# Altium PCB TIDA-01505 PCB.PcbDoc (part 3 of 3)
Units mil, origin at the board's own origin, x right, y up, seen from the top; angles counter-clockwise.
Board outline 7874.02 x 6929.13 mil, 2 copper layers (Top Layer, Bottom Layer), stack 62 mil thick; 307 components, 129 nets, 623 pads, 701 vias.
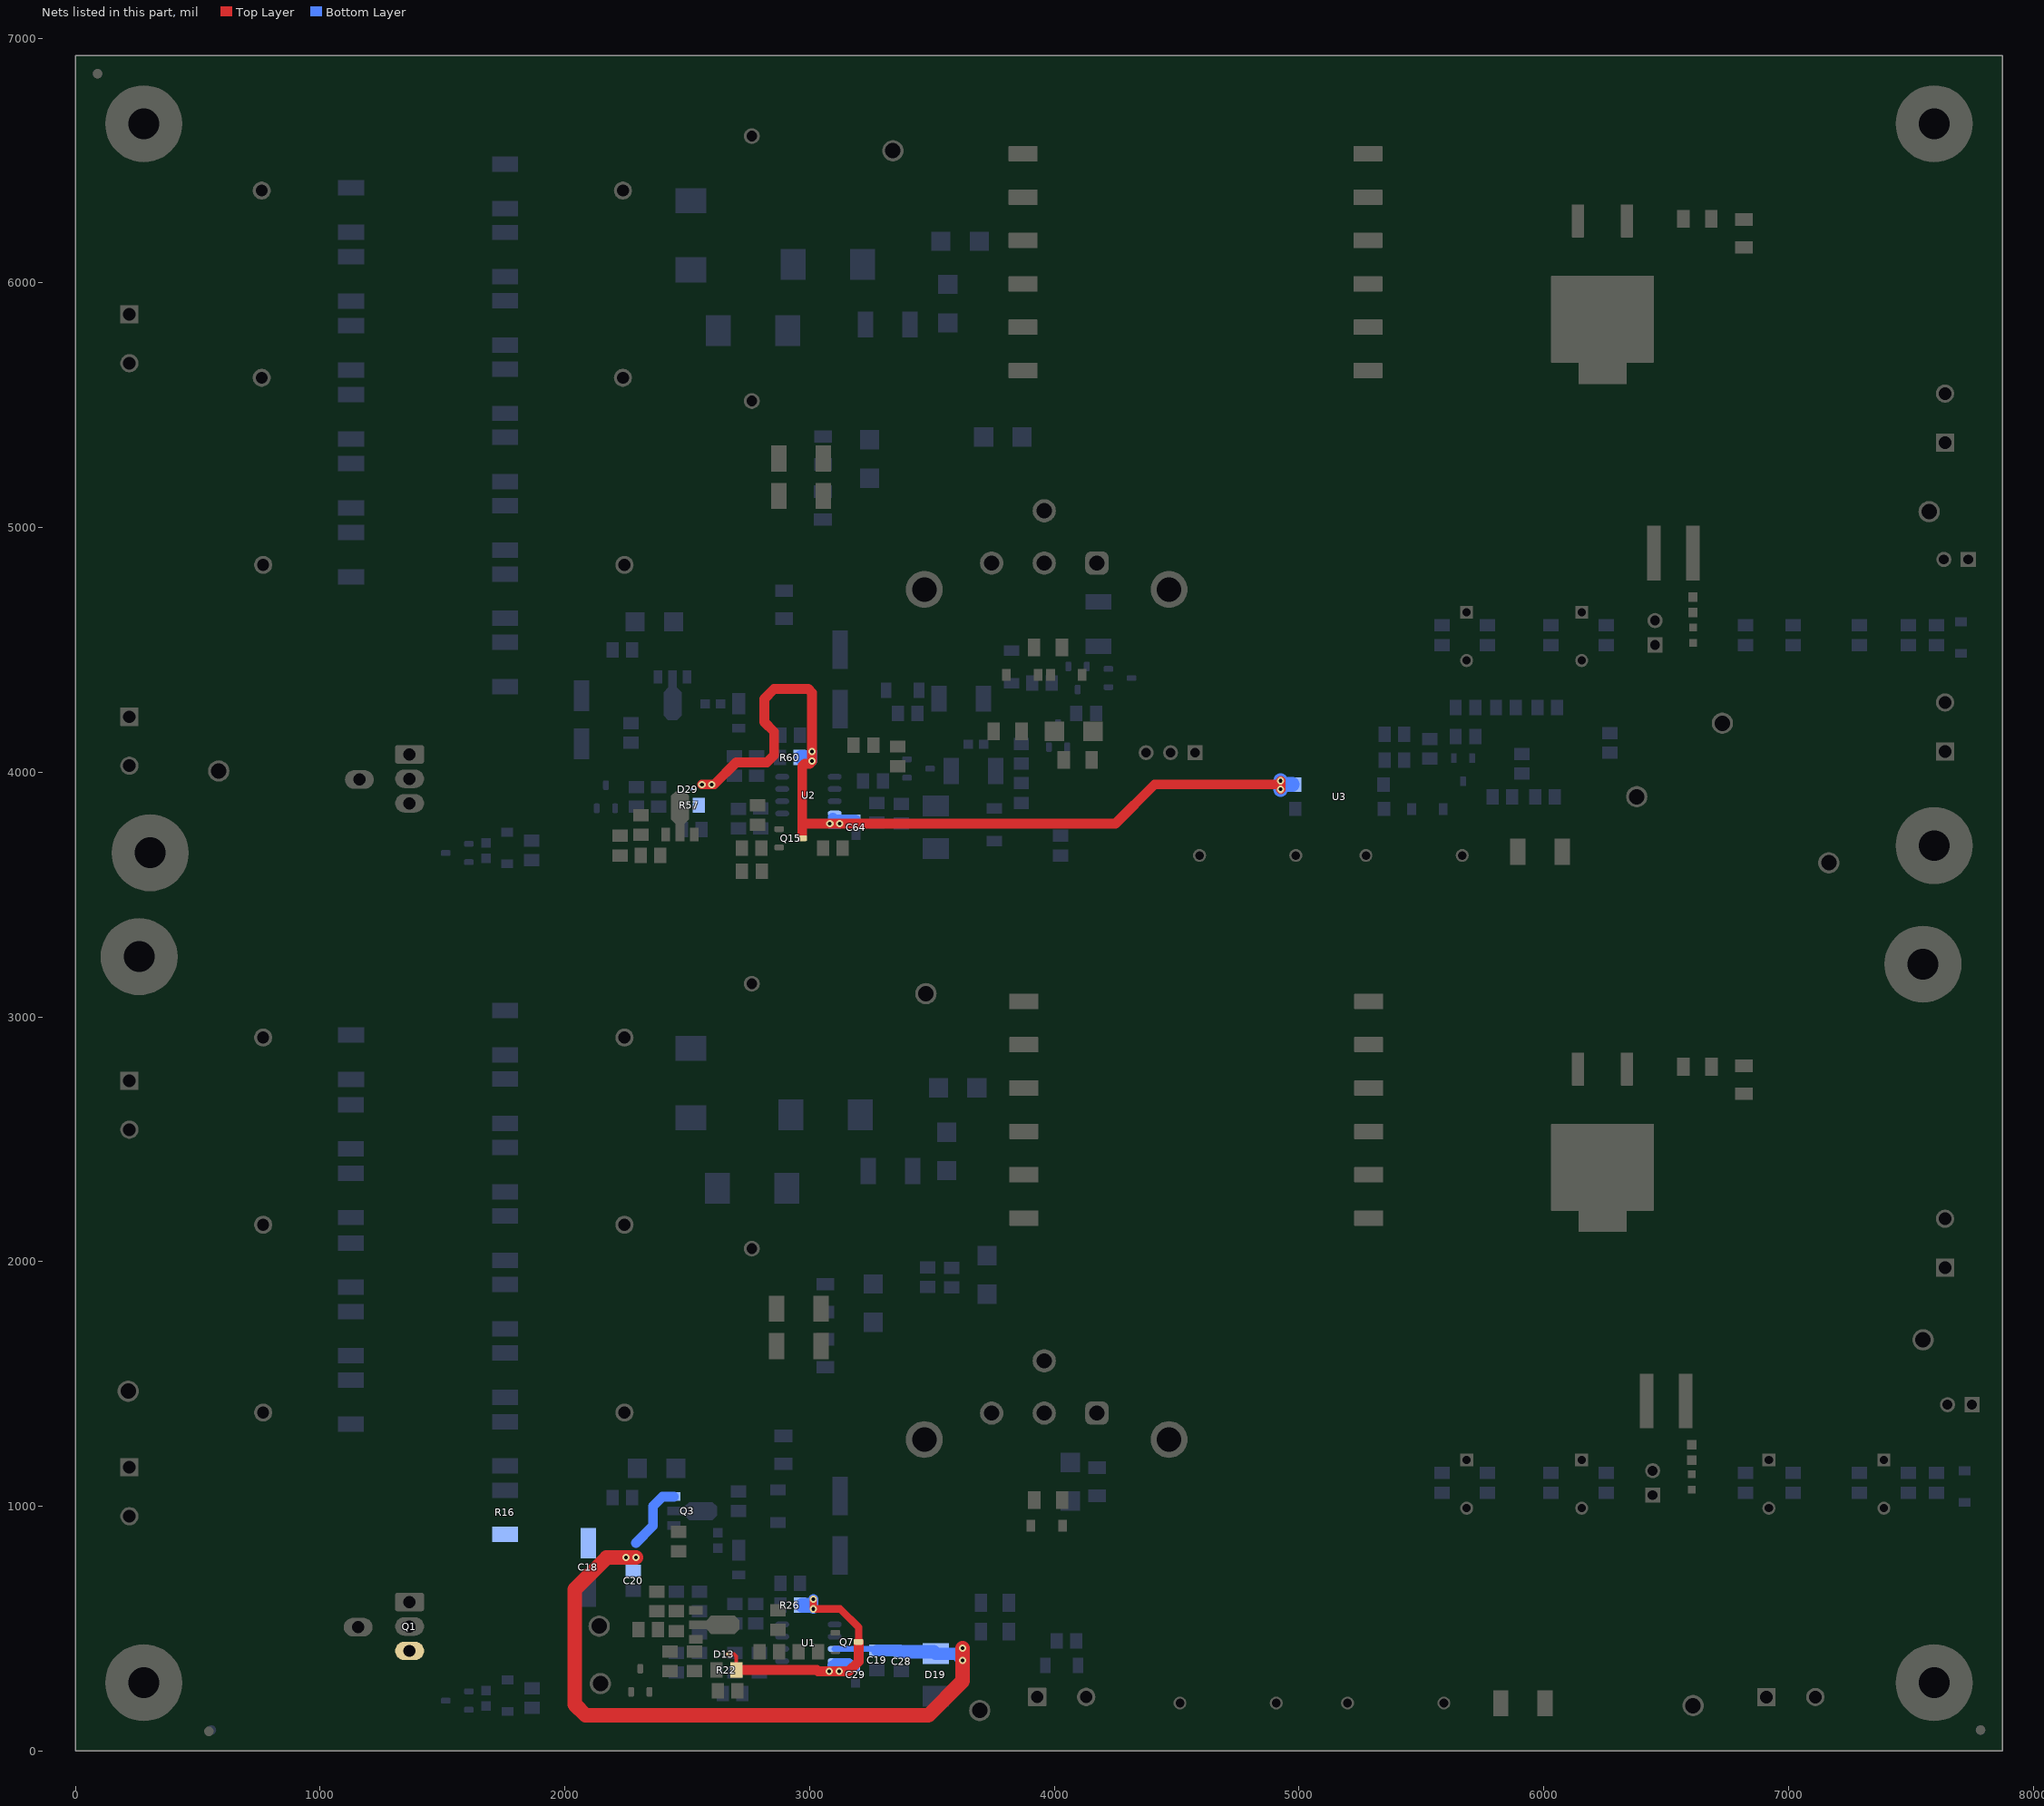
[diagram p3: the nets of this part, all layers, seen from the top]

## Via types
v1: diameter 30, hole 15, Top Layer to Bottom Layer, 666 vias
v2: diameter 20, hole 10, Top Layer to Bottom Layer, 35 vias

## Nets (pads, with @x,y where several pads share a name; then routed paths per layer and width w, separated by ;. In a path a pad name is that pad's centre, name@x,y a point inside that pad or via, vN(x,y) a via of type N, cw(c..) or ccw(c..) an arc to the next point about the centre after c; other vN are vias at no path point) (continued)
VDD_PSR: C18.1 C19.1 C20.1 C28.1 D19.1 Q1.3 Q3.3 R16.1 U1.7 | length 3442.9
  Top Layer w60: v1(2290,790) v1(2250,790) 2170,790 2040,660 2040,190 2085,145 3485,145 3625,285 v1(3625,370) v1(3625,420)
  Bottom Layer w25: U1.7@3102.28,416.65 3268.78,416.65 C19.1@3275,410.43
  Bottom Layer w40: 2290,850 2360,920 2360,1000 2399.06,1039.06 Q3.3@2445.2,1039.06
  Bottom Layer w50: C19.1@3275,410.43 3370,410.43 C28.1@3375,405.43 ; D19.1@3507.01,405.43 D19.1@3515,397.44 3597.56,397.44 v1(3625,370) v1(3625,420)
  Bottom Layer w55: C28.1@3375,405.43 D19.1@3507.01,405.43
VREF: C64.1 D29.1 Q15.3 R57.1 R60.2 U2.8 U3.4 | length 3813.1
  Top Layer w40: v1(2560,3950) v1(2600,3950) 2610,3950 2700,4040 2825,4040 2855,4070 2855,4165 2815,4205 2815,4300 2855,4340 2995,4340 3010,4325 v1(3010,4085) v1(3010,4045) 3000,4035 2980,4035 2970,4025 2970,3790 ; 2970,3745 2970,3790 ; v1(4925,3930) 4925,3950 ; v1(4925,3965) 4925,3950 ; 2970,3790 2970.04,3789.96 v1(3082.56,3789.96) v1(3122.56,3789.96) 4249.96,3789.96 4410,3950 4925,3950
  Bottom Layer w40: 2995,4060 v1(3010,4045) v1(3010,4085) ; v1(3082.56,3789.96) v1(3122.56,3789.96) 3139.06,3806.46 ; 3095,3815 3103.54,3806.46 3139.06,3806.46 ; C64.1@3187.56,3806.46 3139.06,3806.46
  Bottom Layer w60: R60.2@2965,4060 2995,4060 ; v1(4925,3930) v1@4925,3935 ; v1(4925,3965) v1@4925,3935 ; U3.4@4972.55,3950 4940,3950 v1@4925,3935
VREF_PSR: C29.1 D13.1 Q7.3 R22.1 R26.2 U1.8 | length 1353.7
  Top Layer w15: D13.1@2666.54,395.43 2690.12,395.43 2700,385.56 R22.1@2700,330.43
  Top Layer w30: v1(3015,620) v1(3015,580) 3125,580 3199.8,505.2 Q7.3@3199.8,445.39
  Top Layer w40: R22.1@2700,330.43 3029.18,330.43 3034.61,325 v1(3080,325) v1(3120,325) 3160,325 3200,365 3200,445.2 Q7.3@3199.8,445.39
  Bottom Layer w25: U1.8@3102.28,366.65 3162.83,366.65 C29.1@3187.56,341.93
  Bottom Layer w40: 3000,595 v1(3015,580) v1(3015,620) ; v1(3080,325) v1(3120,325) 3136.5,341.5 ; 3092.44,350.04 3100.98,341.5 3136.5,341.5 ; C29.1@3185,341.5 3136.5,341.5
  Bottom Layer w60: R26.2@2970,595 3000,595
pads on no net: FID1.1 FID2.1 FID3.1 FID4.1 FID5.1 FID6.1 H1.1 H2.1 H3.1 H4.1 H5.0 H6.0 H7.0 H8.0 H11.1 H12.0 H13.1 H13.2 H14.1 H14.2 H15.1 H16.0 H17.1 H18.1 H19.0 H20.0 Q1.2 Q6.2 Q9.2 Q14.2 T1.2 T1.7 T1.12 T2.2 T2.7 T2.12 TP6.1

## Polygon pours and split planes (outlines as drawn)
+15Vout on Bottom Layer "BOTTOM_LAYER_+15VOUT_P144" (solid, remove dead copper, pour order 144): 7885,5800 7500,5800 7440,5740 7440,5190 7340,5090 6535,5090 6480,5035 6480,4745 6540,4685 6615,4685 6635,4665 6635,4593.78 6653.78,4575 7859.02,4575 7874.02,4590
Iso_GND on Bottom Layer "BOTTOM_LAYER_ISO_GND_P142" (solid, remove dead copper, pour order 142): 7875,4545 7875,3550.98 7874.02,3550 6090,3550 6045,3595 6045,4170 5850,4365 5290,4365 5220,4435 5220,4505 5260,4545
NetC44_1 on Bottom Layer "BOTTOM_LAYER_NETC44_1_P140" (solid, remove dead copper, pour order 140): 5220,4575 6390,4575 6490,4675 6490,5035 6540,5085 7370,5085 7455,5170 7455,5750 7500,5795 7875,5795 7875,6930 5220.87,6930 5220,6929.13
HV_GND on Bottom Layer "BOTTOM_LAYER_HV_GND_P066" (solid, remove dead copper, pour order 66): 2390,4615 3180,4615 3270,4525 4255,4525 4335,4445 4335,4085 4420,4000 4555,4000 4615,3940 4615,3585 4575,3545 1635,3545 1585,3595 1585,3710 1645,3770 1780,3770 1945,3935 1945,4115 2010,4180 2135,4180 2290,4335 2290,4539.33
Gate_FET on Bottom Layer "BOTTOM_LAYER_GATE_FET_P062" (solid, remove dead copper, pour order 62): 4250,4555 4260,4545 4260,4420 4255,4415 4120,4415 4115,4420 4115,4540 4130,4555
-5V on Bottom Layer "BOTTOM_LAYER_-5V_P060" (solid, remove dead copper, pour order 60): 3950,3900 3965,3915 3995,3915 3995,3855 3972.4,3832.4 3717.6,3832.4 3717.6,3840 3715,3842.6 3715,3880 3735,3900 3755,3900
VREF on Bottom Layer "BOTTOM_LAYER_VREF_P058" (solid, remove dead copper, pour order 58): 2525,3830 2571.56,3830 2581.56,3840 2581.56,3901.56 2595,3915 2620,3915 2625,3920 2625,3955 2610,3970 2525,3970 2510,3955 2510,3908.5 2525,3893.5
NetC61_2 on Bottom Layer "BOTTOM_LAYER_NETC61_2_P056" (solid, remove dead copper, pour order 56): 2205,3885 2195,3875 2195,3835 2200,3830 2485,3830 2495,3840 2495,3930.83 2485.83,3940 2465,3940 2460,3935 2460,3895 2450,3885
NetC42_1 on Bottom Layer "BOTTOM_LAYER_NETC42_1_P052" (solid, remove dead copper, pour order 52): 3295,4655 2605,4655 2565,4615 2565,4410 2550,4395 2550,4345 2795,4345 2875,4425 3375,4425 3415,4385 3415,4210 3425,4200 3465,4200 3485,4220 3485,4465
VDD on Bottom Layer "BOTTOM_LAYER_VDD_P046" (solid, pour order 46): 1330,3910 1315,3895 1315,3850 1330,3835 1665,3835 1750,3920 1750,4185 1815,4250 2200,4250 2242.56,4207.44 2242.56,4182.44 2250,4175 2310,4175 2315,4180 2315,4315 2250,4380 2165,4380 1702.01,4380 1665,4342.99 1665,3970 1605,3910
NetR50_1 on Bottom Layer "BOTTOM_LAYER_NETR50_1_P040" (solid, pour order 40): 1699.29,4660 1812.99,4660 1830,4642.99 1830,4517.99 1812.01,4500 1692.99,4500 1680,4512.99 1680,4643.13
NetQ9_2 on Bottom Layer "BOTTOM_LAYER_NETQ9_2_P038" (solid, pour order 38): 1636.3,4940.51 1807.99,4940.51 1827.99,4920.51 1827.99,4795 1812.99,4780 1630,4780 1615,4795 1615,4921.88
NetR45_1 on Bottom Layer "BOTTOM_LAYER_NETR45_1_P036" (solid, pour order 36): 1700.21,5221.3 1810,5221.3 1830,5201.3 1830,5078.7 1807.09,5055.79 1698.9,5055.79 1680,5074.69 1680,5203.62
NetR43_1 on Bottom Layer "BOTTOM_LAYER_NETR43_1_P034" (solid, pour order 34): 1700.21,5500.51 1810,5500.51 1830,5480.51 1830,5357.91 1802.09,5330 1703.9,5330 1680,5353.9 1680,5482.83
NetR42_1 on Bottom Layer "BOTTOM_LAYER_NETR42_1_P032" (solid, pour order 32): 1700.21,5780.51 1810,5780.51 1830,5760.51 1830,5637.91 1802.09,5610 1703.9,5610 1680,5633.9 1680,5762.83
NetR40_1 on Bottom Layer "BOTTOM_LAYER_NETR40_1_P030" (solid, pour order 30): 1700.21,6060.51 1810,6060.51 1830,6040.51 1830,5917.91 1802.09,5890 1703.9,5890 1680,5913.9 1680,6042.83
NetR38_1 on Bottom Layer "BOTTOM_LAYER_NETR38_1_P020" (solid, pour order 20): 1700.21,6340.51 1810,6340.51 1830,6320.51 1830,6197.91 1802.09,6170 1703.9,6170 1680,6193.9 1680,6322.83
NetC41_2 on Bottom Layer "BOTTOM_LAYER_NETC41_2_P018" (solid, pour order 18): 716.11,5665 840,5665 875,5630 875,5470 925,5420 930,5420 962.92,5387.08 1065.31,5387.08 1073.23,5395 1181.18,5395 1200,5376.18 1200,5245 1185,5230 1066.26,5230 1061.26,5235 965,5235 875,5145 875,4850 820,4795 715,4795 675,4835 675,5628
NetQ9_1 on Bottom Layer "BOTTOM_LAYER_NETQ9_1_P016" (solid, pour order 16): 1192.48,4835 1215,4812.48 1215,4505 1425,4295 1425,4045 1415,4035 1316.11,4035 1306.11,4045 1306.11,4113.89 1305,4115 1305,4175 1045,4435 1045,4485 1045,4810 1070,4835
NetR48_1 on Bottom Layer "BOTTOM_LAYER_NETR48_1_P014" (solid, pour order 14): 1074.85,5115 1181.18,5115 1200,5096.18 1200,4958.82 1186.18,4945 1068.23,4945 1050,4963.23 1050,5093.26
NetR41_1 on Bottom Layer "BOTTOM_LAYER_NETR41_1_P010" (solid, pour order 10): 1066.94,5680 1186.2,5680 1200,5666.2 1200,5526.69 1183.31,5510 1071.26,5510 1050,5531.26 1050,5665.18
HV_DC on Bottom Layer "BOTTOM_LAYER_HV_DC_P000" (solid, remove dead copper, pour order 0): 0,5575 375,5575 450,5650 450,6100 705,6355 1455,6355 1555,6455 1855,6455 1905,6505 1905,6560 1945,6600 2380,6600 2450,6530 2450,6205 2625,6205 2730,6310 2730,6415 2820,6505 3940,6505 3995,6560 3995,6745 3810,6930 685,6930 500,6745 500,6575 410,6485 210,6485 0,6275
NetR37_1 on Bottom Layer "BOTTOM_LAYER_NETR37_1_P004" (solid, pour order 4): 1068.94,6240 1181.18,6240 1200,6221.18 1200,6095 1180,6075 1070,6075 1050,6095 1050,6223.43
NetC38_2 on Bottom Layer "BOTTOM_LAYER_NETC38_2_P006" (solid, pour order 6): 1072.86,5960 1180,5960 1198.76,5941.24 1198.76,5810.45 1178.31,5790 1075,5790 1048.76,5816.24 1048.76,5938.91
HV_IN_PSR on Bottom Layer "BOTTOM_LAYER_HV_IN_PSR_P070" (solid, remove dead copper, pour order 70): 0,2112.77 375,2112.77 450,2187.77 450,2637.77 707.23,2895 1457.23,2895 1555,2992.77 1855,2992.77 1905,3042.77 1905,3097.77 1945,3137.77 2380,3137.77 2450,3067.77 2450,2820 2655,2820 2730,2895 2730,2952.77 2832.23,3055 3940,3055 3995,3110 3995,3282.77 3938.83,3338.94 556.17,3338.94 500,3282.77 500,3112.77 410,3022.76 210,3022.76 0,2812.77
NetC6_2 on Bottom Layer "BOTTOM_LAYER_NETC6_2_P072" (solid, pour order 72): 711.56,2210 829.37,2210 866.26,2173.11 866.26,2008.11 916.26,1958.11 921.26,1958.11 954.18,1925.19 1063.1,1925.19 1067.91,1930 1177.09,1930 1191.26,1915.83 1191.26,1770.63 1180.63,1760 1065,1760 1051.89,1773.11 956.26,1773.11 866.26,1683.11 866.26,1388.11 808.15,1330 709.37,1330 666.26,1373.11 666.26,2169.23
NetC3_2 on Bottom Layer "BOTTOM_LAYER_NETC3_2_P074" (solid, pour order 74): 1066.29,2493.13 1181.87,2493.13 1198.13,2476.87 1198.13,2339.4 1186.87,2328.13 1058.87,2328.14 1048.13,2338.87 1048.13,2477.25
NetR2_1 on Bottom Layer "BOTTOM_LAYER_NETR2_1_P076" (solid, pour order 76): 1064.95,2780 1184.63,2780 1198.78,2765.85 1198.78,2613.37 1190.41,2605 1059.63,2605 1048.78,2615.85 1048.78,2765.85
NetR6_1 on Bottom Layer "BOTTOM_LAYER_NETR6_1_P078" (solid, pour order 78): 1066.44,2215 1186.63,2215 1200,2201.63 1200,2052.01 1187.99,2040 1065,2040 1050,2055 1050,2200.61
NetR14_1 on Bottom Layer "BOTTOM_LAYER_NETR14_1_P080" (solid, pour order 80): 1072.86,1650 1174.96,1650 1200,1624.96 1200,1497.91 1182.09,1480 1072.91,1480 1050,1502.91 1050,1630
NetQ1_1 on Bottom Layer "BOTTOM_LAYER_NETQ1_1_P082" (solid, pour order 82): 1192.91,1370 1215,1347.91 1215,1040.43 1425,830.43 1425,580.43 1415,570.43 1316.11,570.43 1306.11,580.43 1306.11,649.32 1305,650.43 1305,710.43 1045,970.43 1045,1020.43 1045,1345.43 1069.57,1370
NetR3_1 on Bottom Layer "BOTTOM_LAYER_NETR3_1_P084" (solid, pour order 84): 1700.21,2876.3 1810,2876.3 1830,2856.3 1830,2733.7 1811.3,2715 1694.69,2715 1680,2729.69 1680,2858.62
NetR5_1 on Bottom Layer "BOTTOM_LAYER_NETR5_1_P086" (solid, pour order 86): 1700.21,2595.95 1810,2595.95 1830,2575.95 1830,2453.35 1811.65,2435 1694.33,2435 1680,2449.33 1680,2578.27
NetR7_1 on Bottom Layer "BOTTOM_LAYER_NETR7_1_P088" (solid, pour order 88): 1700.21,2315.95 1810,2315.95 1830,2295.95 1830,2173.35 1811.65,2155 1694.33,2155 1680,2169.33 1680,2298.27
NetR8_1 on Bottom Layer "BOTTOM_LAYER_NETR8_1_P090" (solid, pour order 90): 1700.21,2035.95 1810,2035.95 1830,2015.95 1830,1893.35 1811.65,1875 1694.33,1875 1680,1889.33 1680,2018.27
NetR10_1 on Bottom Layer "BOTTOM_LAYER_NETR10_1_P092" (solid, pour order 92): 1700.21,1756.73 1810,1756.73 1830,1736.73 1830,1614.13 1807.09,1591.22 1698.9,1591.22 1680,1610.12 1680,1739.05
NetQ1_2 on Bottom Layer "BOTTOM_LAYER_NETQ1_2_P094" (solid, pour order 94): 1636.3,1475.95 1807.99,1475.95 1827.99,1455.95 1827.99,1330.43 1812.99,1315.43 1630,1315.43 1615,1330.43 1615,1457.31
NetR13_1 on Bottom Layer "BOTTOM_LAYER_NETR13_1_P096" (solid, pour order 96): 1699.29,1195.43 1812.99,1195.43 1830,1178.43 1830,1053.43 1812.01,1035.43 1692.99,1035.43 1680,1048.43 1680,1178.56
VDD_PSR on Bottom Layer "BOTTOM_LAYER_VDD_PSR_P098" (solid, pour order 98): 1330,445.43 1315,430.43 1315,385.43 1330,370.43 1675.43,370.43 1775,470 1775,745.43 1815,785.43 2200,785.43 2242.56,742.87 2242.56,717.87 2250,710.43 2310,710.43 2315,715.43 2315,850.43 2250,915.43 2165,915.43 1702.01,915.43 1665,878.42 1665,505.43 1605,445.43
HV_GND_PSR on Bottom Layer "BOTTOM_LAYER_HV_GND_PSR_P118" (solid, remove dead copper, pour order 118): 3610,1970.45 3610,2065 3580,2095 3390,2095 3360,2065 3360,1960 3370,1950 3587.5,1950
+5V_PSR on Bottom Layer "BOTTOM_LAYER_+5V_PSR_P120" (solid, remove dead copper, pour order 120): 3625,1905 3610,1920 3420,1920 3395,1895 3395,1840 3420,1815 3810,1815 3825,1830 3825,1875 3795,1905
+5V_PSR on Bottom Layer "BOTTOM_LAYER_+5V_PSR_P124" (solid, remove dead copper, pour order 124): 4125,575 4065,515 4065,185 4130,120 4300,120 4350,170 4350,525 4300,575
+20V_PSR on Bottom Layer "BOTTOM_LAYER_+20V_PSR_P128" (solid, remove dead copper, pour order 128): 2415,1225 2460,1270 2715,1270 2785,1200 3150,1200 3215,1135 3215,995 3185,965 2940,965 2870,1035 2685,1035 2680,1040 2680,1095 2660,1115 2435,1115 2415,1135
HV_GND_PSR on Bottom Layer "BOTTOM_LAYER_HV_GND_PSR_P130" (solid, remove dead copper, pour order 130): 2313.73,1149.96 3103.73,1149.96 3213.73,1039.96 4198.73,1039.96 4258.73,979.96 4258.73,619.96 4343.73,534.96 4478.73,534.96 4538.73,474.96 4538.73,119.96 4498.73,79.96 1558.73,79.96 1508.73,129.96 1508.73,244.96 1568.73,304.96 1703.73,304.96 1868.73,469.96 1868.73,649.96 1933.73,714.96 2058.73,714.96 2248.73,904.96 2248.73,1100.78
NetC10_1 on Bottom Layer "BOTTOM_LAYER_NETC10_1_P168" (solid, remove dead copper, pour order 168): 5220.29,1110.43 6390.29,1110.43 6490.29,1210.43 6490.29,1570.43 6540.29,1620.43 7370.29,1620.43 7455.29,1705.43 7455.29,2285.43 7500.29,2330.43 7875.29,2330.43 7875.29,3141.42 7627.71,3345 5270,3345 5223.15,3298.15
Iso_GND_PSR on Bottom Layer "BOTTOM_LAYER_ISO_GND_PSR_P170" (solid, remove dead copper, pour order 170): 7875.29,1080.43 7875.29,86.42 7874.3,85.43 6090.29,85.43 6045.29,130.43 6045.29,705.43 5850.29,900.43 5290.29,900.43 5220.29,970.43 5220.29,1040.43 5260.29,1080.43
+15Vout_PSR on Bottom Layer "BOTTOM_LAYER_+15VOUT_PSR_P172" (solid, remove dead copper, pour order 172): 7885.29,2335.43 7500.29,2335.43 7440.29,2275.43 7440.29,1725.43 7340.29,1625.43 6535.29,1625.43 6480.29,1570.43 6480.29,1280.43 6540.29,1220.43 6615.29,1220.43 6635.29,1200.43 6635.29,1129.21 6654.07,1110.43 7859.3,1110.43 7874.3,1125.43
+15Vout on Top Layer "TOP_LAYER_+15VOUT_P146" (solid, remove dead copper, pour order 146): 7880.98,5800 7495.98,5800 7435.98,5740 7435.98,5190 7335.98,5090 6530.98,5090 6475.98,5035 6475.98,4745 6535.98,4685 6610.98,4685 6630.98,4665 6630.98,4593.78 6635.98,4588.78 7868.78,4588.78 7870,4590
Iso_GND on Top Layer "TOP_LAYER_ISO_GND_P134" (solid, remove dead copper, pour order 134): 5220,6030 5620,6030 5670,5980 5670,5025 5600,4955 5595,4955 5505,4865 5505,4595 5555,4545 5625,4545 5630,4550 7874.02,4550 7875,4549.02 7875,3545 7870,3550 6090,3550 6045,3595 6045,4100 5845,4300 5355,4300 5220,4435
NetC44_1 on Top Layer "TOP_LAYER_NETC44_1_P138" (solid, remove dead copper, pour order 138): 6355,4620 6480,4745 6480,5035 6530,5085 7365,5085 7455,5175 7455,5755 7500,5800 7874.02,5800 7870,5804.02 7870,6935 7865,6930 5220,6930 5220,4995 5595,4620
NetD25_1 on Top Layer "TOP_LAYER_NETD25_1_P132" (solid, remove dead copper, pour order 132): 5220,6160 5240,6140 5610,6140 5655,6185 6555,6185 6595,6225 6595,6415 6535,6475 5255,6475 5220,6440
HV_GND on Top Layer "TOP_LAYER_HV_GND_P068" (solid, remove dead copper, pour order 68): 2390,4615 3180,4615 3270,4525 4255,4525 4335,4445 4335,4085 4420,4000 4555,4000 4615,3940 4615,3585 4575,3545 1635,3545 1585,3595 1585,3710 1645,3770 1780,3770 1945,3935 1945,4115 2010,4180 2135,4180 2305,4350 2305,4550.68
SW_node on Top Layer "TOP_LAYER_SW_NODE_P064" (solid, remove dead copper, pour order 64): 3785,6205 4185,6205 4250,6140 4250,5170 4180,5100 4055,5100 3980,5025 3935,5025 3900,5060 3900,5235 3965,5300 4100,5300 4100,6070 4030,6140 3960,6140 3780,6140 3780,6200
NetQ9_2 on Top Layer "TOP_LAYER_NETQ9_2_P042" (solid, pour order 42): 1190,4010 1205,3995 1210,3995 1220,3985 1220,3955 1195,3930 1025,3930 910,4045 910,4300 1545,4935 1675,4935 1705,4905 1705,4790 1675,4760 1620,4760 1090,4230 1090,4045 1125,4010
NetC38_2 on Top Layer "TOP_LAYER_NETC38_2_P008" (solid, pour order 8): 2300,5575 2325.51,5600.51 2325.51,6350 2250.51,6425 2050,6425 1950,6325 1950,6100 1816.65,5966.65 1075,5966.65 1025,5916.65 1025,5800 1075,5750 1950,5750 2125,5575
HV_DC on Top Layer "TOP_LAYER_HV_DC_P002" (solid, pour order 2): 3929,6821 3994,6756 3994,6526 3964,6496 2789,6496 2709,6576 2709,6751 2779,6821
HV_GND on Top Layer "TOP_LAYER_HV_GND_P048" (solid, remove dead copper, pour order 48): 145,4405 50,4310 50,3900 150,3800 620,3800 665,3845 665,4565 1260,5160 1975,5160 2175,4960 2175,4825 2205,4795 2305,4795 2305,4535 2580.29,4535 2782.5,4720 2902.5,4840 2905,5460 2805,5560 2730,5560 2592.83,5422.83 2505,5335 755,5335 260,4840 260,4410 145,4410 145,4400
CS_Rs on Top Layer "TOP_LAYER_CS_RS_P050" (solid, remove dead copper, pour order 50): 3760,4755 3790,4785 3790,4910 3725,4975 3360,4975 3230,5105 3230,5285 3175,5340 3030,5340 3020,5330 3020,5055 3320,4755
HV_GND_PSR on Top Layer "TOP_LAYER_HV_GND_PSR_P100" (solid, remove dead copper, pour order 100): 0,1270 0,879.18 45,845 540,845 657.09,962.09 657.09,1100.39 1252.09,1695.39 1967.09,1695.39 2167.09,1495.39 2167.09,1360.39 2197.09,1330.39 2297.09,1330.39 2839.68,1330.39 2894.59,1375.39 2897.09,1995.39 2802.48,2090 2663.86,2090 2532.09,1958.23 2444.25,1870.39 747.09,1870.39 255,1378.31 166.57,1378.31
NetC3_2 on Top Layer "TOP_LAYER_NETC3_2_P102" (solid, pour order 102): 2300,2115 2325.51,2140.51 2325.51,2890 2250.51,2965 2050,2965 1950,2865 1950,2640 1816.65,2506.65 1075,2506.65 1025,2456.65 1025,2340 1075,2290 1950,2290 2125,2115
NetQ1_2 on Top Layer "TOP_LAYER_NETQ1_2_P104" (solid, pour order 104): 1184.96,545.39 1199.96,530.39 1204.96,530.39 1214.96,520.39 1214.96,490.39 1189.96,465.39 1019.96,465.39 904.96,580.39 904.96,835.39 1539.96,1470.39 1669.96,1470.39 1699.96,1440.39 1699.96,1325.39 1669.96,1295.39 1614.96,1295.39 1084.96,765.39 1084.96,580.39 1119.96,545.39
SW_PSR on Top Layer "TOP_LAYER_SW_PSR_P108" (solid, remove dead copper, pour order 108): 3776.22,2741.34 4176.22,2741.34 4241.22,2676.34 4241.22,1706.34 4171.22,1636.34 4071.34,1636.34 3985,1550 3937.56,1550 3891.22,1596.34 3891.22,1736.22 3960,1805 4091.22,1805 4091.22,2606.34 4021.22,2676.34 3951.22,2676.34 3771.22,2676.34 3771.22,2736.34
HV_IN_PSR on Top Layer "TOP_LAYER_HV_IN_PSR_P110" (solid, pour order 110): 3932.15,3356.71 3997.15,3291.71 3997.15,3061.71 3967.15,3031.71 2792.15,3031.71 2712.15,3111.71 2712.15,3286.71 2782.15,3356.71
CS_Rs_PSR on Top Layer "TOP_LAYER_CS_RS_PSR_P112" (solid, remove dead copper, pour order 112): 3760,1280.43 3790,1310.43 3790,1435.43 3725,1500.43 3360,1500.43 3230,1630.43 3230,1810.43 3180.43,1860 3023,1860 3015,1852 3015,1585.43 3320,1280.43
HV_GND on Top Layer "TOP_LAYER_HV_GND_P114" (solid, remove dead copper, pour order 114): 3820,5790 3812.5,5785 3640,5785 3550,5695 3550,5495 3470,5415 2880,5415 2805,5490 2805,5560 3370,5560 3410,5600 3410,5760 3500,5850 3835,5850 3835,5835
HV_GND_PSR on Top Layer "TOP_LAYER_HV_GND_PSR_P116" (solid, remove dead copper, pour order 116): 3820,2331.67 3810,2320 3590,2320 3500,2230 3500,1980 3470,1950 2880,1950 2790,2040 2790,2090 3360,2090 3400,2130 3400,2285 3500,2385 3820,2385 3820,2340
HV_GND_PSR on Top Layer "TOP_LAYER_HV_GND_PSR_P122" (solid, remove dead copper, pour order 122): 2310,1150.43 3100,1150.43 3210,1040.43 4195,1040.43 4255,980.43 4255,620.43 4340,535.43 4475,535.43 4535,475.43 4535,120.43 4495,80.43 1555,80.43 1505,130.43 1505,245.43 1565,305.43 1700,305.43 1865,470.43 1865,650.43 1930,715.43 2055,715.43 2245,905.43 2245,1101.25
NetD4_1 on Top Layer "TOP_LAYER_NETD4_1_P156" (solid, remove dead copper, pour order 156): 5223.15,2695.71 5243.15,2675.71 5613.15,2675.71 5658.15,2720.71 6558.15,2720.71 6598.15,2760.71 6598.15,2950.71 6538.15,3010.71 5258.15,3010.71 5223.15,2975.71
+15Vout_PSR on Top Layer "TOP_LAYER_+15VOUT_PSR_P162" (solid, remove dead copper, pour order 162): 7884.13,2335.71 7499.13,2335.71 7439.13,2275.71 7439.13,1725.71 7339.13,1625.71 6534.13,1625.71 6479.13,1570.71 6479.13,1280.71 6539.13,1220.71 6614.13,1220.71 6634.13,1200.71 6634.13,1129.49 6639.13,1124.49 7871.93,1124.49 7873.15,1125.71
Iso_GND_PSR on Top Layer "TOP_LAYER_ISO_GND_PSR_P164" (solid, remove dead copper, pour order 164): 5223.15,2565.71 5623.15,2565.71 5673.15,2515.71 5673.15,1560.71 5603.15,1490.71 5598.15,1490.71 5508.15,1400.71 5508.15,1130.71 5558.15,1080.71 5628.15,1080.71 5633.15,1085.71 7877.17,1085.71 7878.15,1084.72 7878.15,80.71 7873.15,85.71 6034.29,85.71 5975,145 5975,708.86 5848.15,835.71 5358.15,835.71 5223.15,970.71
NetC10_1 on Top Layer "TOP_LAYER_NETC10_1_P166" (solid, remove dead copper, pour order 166): 6358.15,1155.71 6483.15,1280.71 6483.15,1570.71 6533.15,1620.71 7368.15,1620.71 7458.15,1710.71 7458.15,2290.71 7503.15,2335.71 7877.17,2335.71 7873.15,2339.72 7873.15,3125.99 7622.86,3345 5270,3345 5223.15,3298.15 5223.15,1530.71 5598.15,1155.71

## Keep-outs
Keep-Out Layer:
  lines w10: 0,0 0,3450 70,3450 70,3480 0,3480 0,6929.13 4475,6929.13 4475,5275 4625,5275 4625,6929.13 7874.02,6929.13 7874.02,3480 7750,3480 7750,3450 7874.02,3450 7874.02,0 0,0 ; 550,3450 7250,3450 7250,3480 550,3480 550,3450 ; 1170,370 1201.11,370 1281.11,450 1281.11,568.89 1200,650 1175,625 1250,550 1250,475 1170,395 1170,370 ; 1170,3840 1201.11,3840 1281.11,3920 1281.11,4038.89 1200,4120 1175,4095 1250,4020 1250,3945 1170,3865 1170,3840 ; 3815,1548.89 3895,1468.89 4013.89,1468.89 4095,1550 4070,1575 3995,1500 3920,1500 3840,1580 3815,1580 3815,1548.89 ; 3820,5020 3900,4940 4018.89,4940 4100,5021.11 4075,5046.11 4000,4971.11 3925,4971.11 3845,5051.11 3820,5051.11 3820,5020 ; 4475,1790 4625,1790 4625,3429.13 4475,3429.13 4475,1790 ; 5125,3750 5200,3750 5200,4050 5125,4050 5125,3750
  text ".Layer_Name" at 577,-858.49 h60

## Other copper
Top Layer:
  pour cut-out: 710,4994.57 820,4994.57 925,4889.57 1005,4889.57 1005,4829.57 827.5,4652.07 683.38,4579.57 683.38,4711.18 605,4789.57 605,4889.57
  pour cut-out: 710,1530 820,1530 925,1425 1005,1425 1005,1365 827.5,1187.5 683.38,1115 683.38,1246.62 605,1325 605,1425
  pour cut-out: 7880.18,3639.82 7835,3685 7765,3685 7695,3615 7395,3615 7255,3475 7255,3340 7435,3160 7690,3160 7765,3085 7873.47,3085
  text ".Layer_Name" at 577,-858.49 h60
Bottom Layer:
  pour cut-out: 7880.18,3639.82 7835,3685 7765,3685 7695,3615 7395,3615 7250,3470 7250,3350 7440,3160 7690,3160 7760,3090 7873.53,3090
  text ".Layer_Name" at 577,-858.49 h60

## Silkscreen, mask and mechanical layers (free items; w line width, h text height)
Top Overlay:
  region: 6845,6835 6545,6835 6545,6735 6845,6735
  lines w10: 4550,0 4550,60 ; 4550,330 4550,770 ; 4550,3490 4550,3530 ; 4550,3800 4550,3910 ; 4550,5245 4550,5270 ; 4555,4165 4555,4245 ; 5590,-5 5590,55 ; 5590,325 5590,765 ; 5660,3485 5660,3525 ; 5660,3795 5660,4240
  lines w30: 450,3465 520,3465 ; 7280,3465 7380,3465
  text "'.PRJ_Number'.PCB_Rev" at 5525,6740 h150
  text "HV-DC" at 3250,6385 h35
  text "SW_ / node" at 3635,6265 h35
  text "+15Vout" at 7580,5690 h35
  text "HV_DC" at 100,5460 h35
  text "40V-1kVin" at 130,5330 h35
  text "SW_ / node" at 3735,5085 h35
  text "Rsense" at 2800,4985 h35
  text "+" at 7620,4765 h35
  text "-" at 7735,4765 h35
  text "High Voltage" at 4975,4705 h72.83
  text "40V - 1kV Input Flyback  / with Opto-Coupler" at 700,4230 h60
  text "Level Shifter  / Supply Input" at 4665,4020 h35
  text "-5V HV_GND +20V" at 4250,3955 h35
  text "Iso_GND" at 7505,3910 h35
  text "HV_GND" at 515,3860 h35
  text "HV_GND" at 75,3855 h35
  text "'.PRJ_Number'.PCB_Rev" at 5585,3270 h150
  text "HV_IN" at 3370,2950 h35
  text "SW_ / node" at 3645,2810 h35
  text "+15Vout" at 7565,2315 h35
  text "40V-1kVin" at 95,2285 h35
  text "High Voltage" at 90,1695 h72.83
  text "SW_ / node" at 3740,1625 h35
  text "Rsense" at 2745,1520 h35
  text "+" at 7640,1310 h35
  text "-" at 7755,1310 h35
  text "40V - 1kV Input Flyback  / Primiary Side Regulated" at 680,765 h60
  text "Iso_GND" at 6935,465 h35
  text ".Layer_Name" at 577,-858.49 h60
Bottom Overlay:
  lines w30: 450,3465 520,3465 ; 7280,3465 7380,3465
  text "High Voltage" at 2755,4880 h72.83
  text "High Voltage" at 2695,1405 h72.83
  text ".Layer_Name" at 577,-858.49 h60
Top Paste:
  text ".Layer_Name" at 577,-858.49 h60
Bottom Paste:
  text ".Layer_Name" at 577,-858.49 h60
Top Solder:
  text ".Layer_Name" at 577,-858.49 h60
  text ".Layer_Name" at 577,-858.49 h60
Bottom Solder:
  text ".Layer_Name" at 577,-858.49 h60
Drill Guide:
  text ".Layer_Name" at 577,-858.49 h60
M1 Board Outline:
  lines w10: 0,0 0,3450 70,3450 70,3480 0,3480 0,6929.13 4475,6929.13 4475,5275 4625,5275 4625,6929.13 7874.02,6929.13 7874.02,3480 7750,3480 7750,3450 7874.02,3450 7874.02,0 0,0 ; 550,3450 7250,3450 7250,3480 550,3480 550,3450 ; 1170,370 1201.11,370 1281.11,450 1281.11,568.89 1200,650 1175,625 1250,550 1250,475 1170,395 1170,370 ; 1170,3840 1201.11,3840 1281.11,3920 1281.11,4038.89 1200,4120 1175,4095 1250,4020 1250,3945 1170,3865 1170,3840 ; 3815,1548.89 3895,1468.89 4013.89,1468.89 4095,1550 4070,1575 3995,1500 3920,1500 3840,1580 3815,1580 3815,1548.89 ; 3820,5020 3900,4940 4018.89,4940 4100,5021.11 4075,5046.11 4000,4971.11 3925,4971.11 3845,5051.11 3820,5051.11 3820,5020 ; 4475,1790 4625,1790 4625,3429.13 4475,3429.13 4475,1790 ; 5125,3750 5200,3750 5200,4050 5125,4050 5125,3750
  text ".Layer_Name" at 577,-858.49 h60
M2 Board Dimensions:
  rectangle: 0,-275 125,-150
  rectangle: 125,-400 500,-275
  lines w7: 0,-275 1000,-275 ; 125,-400 125,-150 ; 250,-400 250,-150 ; 500,-400 500,-150 ; 750,-400 750,-150 ; 0,-400 1000,-400 1000,-150 0,-150 0,-400
  text ".Layer_Name" at 577,-858.49 h60
M3 3D STEP Top:
  text ".Layer_Name" at 577,-858.49 h60
M4 3D STEP Bottom:
  text ".Layer_Name" at 577,-858.49 h60
M5 Assembly Top:
  lines w10: -292,-930.17 6308,-930.17 ; -292,-726.83 6310,-726.83 ; -292,-523.5 -292,-1133.5 3713,-1133.5 6310,-1133.5 6310,-523.5 -291.5,-523.5 -291.5,-1133.5 1284,-1133.5 ; 2173,-1133.5 2173,-523.5 ; 3440,-726.83 3440,-523.5 ; 4280,-726.83 4280,-523.5 ; 4902,-1140 4902,-937.17
  text "COMPONENTS MARKED 'DNP' SHOULD NOT BE POPULATED." at 1153.5,-318.5 h60
  text "ASSEMBLY VARIANT:" at 1153,-434 h60
  text ".VariantName" at 2189,-434 h60
  text "PCB VIEWED FROM TOP SIDE" at -228.5,-655.67 h60
  text "BOARD #:" at 2248,-655.67 h60
  text ".PRJ_Number" at 2793.5,-655.67 h60
  text "REV:" at 3638,-655.67 h60
  text ".PCB_Rev" at 3929.5,-655.67 h60
  text "SVN REV:" at 4476,-655.67 h60
  text ".VersionControl_RevNumber" at 4982,-655.67 h60
  text "TID #:" at 2248,-859 h60
  text ".TID" at 2793.5,-859 h60
  text "PLOT NAME =" at -228.5,-1064.34 h60
  text ".plot_File_Name" at 577,-1064.34 h60
  text "GENERATED    :" at 2250,-1064.34 h60
  text ".Print_Date" at 3119.5,-1064.34 h60
  text ".Print_Time" at 3848.5,-1064.34 h60
  text "TEXAS INSTRUMENTS" at 5113,-1064.34 h60
M6 Assembly Bottom:
  lines w10: -292.5,-727.33 6309.5,-727.33 ; -290.5,-930.67 6309.5,-930.67 ; 1115.5,-1140.5 1115.5,-937.67 ; 1737.5,-727.33 1737.5,-524 ; 2577.5,-727.33 2577.5,-524 ; 3844.5,-1134 3844.5,-524 ; 4733.5,-1134 6309,-1134 6309,-524 -292.5,-524 -292.5,-1134 2304.5,-1134 6309.5,-1134 6309.5,-524
  text "COMPONENTS MARKED 'DNP' SHOULD NOT BE POPULATED." at 6102,-318 h60
  text ".VariantName" at 5058,-434 h60
  text "ASSEMBLY VARIANT:" at 6097,-434 h60
  text ".VersionControl_RevNumber" at 1035.5,-656.17 h60
  text "SVN REV:" at 1541.5,-656.17 h60
  text ".PCB_Rev" at 2088,-656.17 h60
  text "REV:" at 2379.5,-656.17 h60
  text ".PRJ_Number" at 3224,-656.17 h60
  text "BOARD #:" at 3769.5,-656.17 h60
  text "PCB VIEWED FROM BOTTOM SIDE" at 6246,-656.17 h60
  text ".TID" at 3224,-859.5 h60
  text "TID #:" at 3769.5,-859.5 h60
  text "TEXAS INSTRUMENTS" at 904.5,-1064.84 h60
  text ".Print_Time" at 2169,-1064.84 h60
  text ".Print_Date" at 2898,-1064.84 h60
  text "GENERATED    :" at 3767.5,-1064.84 h60
  text ".plot_File_Name" at 5440.5,-1064.84 h60
  text "PLOT NAME =" at 6246,-1064.84 h60
M9 Title Sheet:
  drawing of 57 lines, arcs and shapes, not listed
  text "1" at 739.84,8036.5 h70
  text "2" at 3235.5,8036.5 h70
  text "3" at 5724.84,8036.5 h70
  text "4" at 8231.51,8036.5 h70
  text "5" at 10730.5,8036.5 h70
  text "6" at 13235.5,8036.5 h70
  text "A" at -416.5,6893.5 h70
  text "A" at 14383.5,6893.5 h70
  text "B" at -416.5,4513.5 h70
  text "B" at 14383.5,4513.5 h70
  text "C" at -416.5,2138.5 h70
  text "C" at 14383.5,2138.5 h70
  text "PROJECT TITLE:" at 11343.5,277.5 h45
  text ".PRJ_Title" at 11393.5,144.17 h70
  text "DESIGNED FOR:" at 11343.5,-23.5 h45
  text ".PRJ_Customer" at 11393.5,-163.5 h70
  text "D" at -416.5,-231.5 h70
  text "D" at 14383.5,-231.5 h70
  text "FILE NAME:" at 11343.5,-323.5 h45
  text ".PCB_File_Name_No_Path" at 11393.5,-443.5 h70
  text "Texas Instruments (TI) and/or its licensors do not warrant the accuracy or completeness of this specification" at 6374,-605.34 h45
  text "ENGINEER:" at 11343.5,-613.5 h45
  text "LAYOUT BY:" at 12848.5,-613.5 h45
  text "or any information contained therein. TI and/or its licensors do not warrant that this design will meet" at 6329.01,-718 h45
  text ".PRJ_Engineer" at 11393.5,-768.49 h70
  text ".PCB_Layout" at 12899,-768.49 h70
  text "the specifications, will be suitable for your application or fit for any particular purpose, or will operate in" at 6329.01,-830.67 h45
  text ".Layer_Name" at 577,-858.49 h60
  text "ALTIUM DESIGNER VERSION:" at 12848.5,-923.5 h45
  text "an implementation. TI and/or its licensors do not warrant that the design is production worthy. You should" at 6329.01,-943.33 h45
  text "completely validate and test your design implementation to confirm the system functionality for your application." at 6374,-1056 h45
  text ".print_Scale" at 11393.5,-1056.83 h70
  text ".Application_BuildNumber" at 12899,-1056.83 h70
  text "1" at 739.84,-1263.5 h70
  text "2" at 3235.5,-1263.5 h70
  text "3" at 5724.84,-1263.5 h70
  text "4" at 8231.51,-1263.5 h70
  text "5" at 10730.5,-1263.5 h70
  text "6" at 13235.5,-1263.5 h70
M10 Fab Notes:
  drawing of 173 lines, arcs and shapes, not listed
  text "DESIGN INFORMATION" at 12378.02,6201 h60
  text "MIN. TRACK WIDTH:" at 11733.46,6021 h60
  text "8" at 12829.7,6021 h60
  text "MIL" at 12984.46,6021 h60
  text "MIN. CLEARANCE:" at 11733.46,5889 h60
  text "0.2" at 12769.7,5889 h60
  text "mm" at 12984.46,5889 h60
  text "MIN. VIA PAD SIZE:" at 11733.46,5757 h60
  text "24" at 12799.71,5757 h60
  text "MIL" at 12984.46,5757 h60
  text "0.05mm (2MIL)" at 12428.46,5615.29 h60
  text "MINIMUM ANNULAR RING" at 11404.23,5611 h60
  text "EXTERNAL" at 13136.46,5611 h60
  text "PER" at 11604.23,5493 h60
  text "IPC-D-275 CLASS 2 LEVEL C" at 11824.23,5493 h60
  text "MIL, HOLES" at 13312.46,5380.71 h60
  text "+/-" at 12920,5380 h60
  text "+/-" at 13774,5380 h60
  text "REGISTRATION TOLERANCES:" at 11404.23,5375 h60
  text "METAL" at 12604,5375 h60
  text "5" at 13180.2,5375 h60
  text "3" at 14013.2,5375 h60
  text "MIL" at 14129.46,5375 h60
  text "+/-" at 13774,5262 h60
  text "HOLE SIZE TOLERANCE (UNLESS OTHERWISE SPECIFIED):" at 11404.23,5257 h60
  text "3" at 14013.2,5257 h60
  text "MIL" at 14129.46,5257 h60
  text "MATERIAL:" at 11329.46,5047.54 h60
  text "FR-4 High Tg" at 12315.9,4907.21 h60
  text "FR-408" at 11750.46,4898.64 h60
  text "OTHER" at 13238.46,4898.64 h60
  text "X" at 12161,4895 h60
  text "62 MIL (1.6mm) +/-10%" at 12070.56,4735.92 h60
  text "THICKNESS:" at 11404.23,4731.64 h60
  text "X" at 11942.4,4731.64 h60
  text "OTHER" at 13355.46,4731.64 h60
  text "TOLERANCE:" at 11404.23,4573.64 h60
  text "X" at 12243.53,4573.64 h60
  text "ANSI IPC-6012 TYPE 3 CLASS 2" at 12430.48,4573.64 h60
  text "OTHER +/-" at 12430.46,4417.64 h60
  text "BOW & TWIST:" at 11404.23,4260.64 h60
  text "X" at 12243.53,4260.64 h60
  text "ANSI IPC-6012 TYPE 3 CLASS 2" at 12430.48,4260.64 h60
  text "OTHER +/-" at 12430.46,4102.13 h60
  text "DRILLING:" at 11329.46,3963.64 h60
  text "REFERENCE:" at 11404.23,3846.64 h60
  text "X" at 12052.46,3846.64 h60
  text "AS SHOWN" at 12239.46,3846.64 h60
  text "X" at 12953.46,3846.64 h60
  text "NC_DRILL FILES" at 13090.46,3846.64 h60
  text "PTH COPPER THICKNESS:" at 11404.23,3688.64 h60
  text "X" at 12534.46,3688.64 h60
  text "20-30 um" at 12671.46,3688.64 h60
  text "OTHER" at 13388.46,3688.64 h60
  text "BOARD FINISH:" at 11329.46,3529.64 h60
  text "SILKSCREEN:" at 11484.68,3411.64 h60
  text "X" at 12433.46,3411.64 h60
  text "TOP" at 12559.46,3411.64 h60
  text "X" at 12943.46,3411.64 h60
  text "BOTTOM" at 13070.46,3411.64 h60
  text "SILKSCREEN COLOR:" at 11484.68,3244.64 h60
  text "X" at 12432.42,3244.64 h60
  text "WHITE" at 12559.46,3244.64 h60
  text "OTHER" at 13070.46,3244.64 h60
  text "X" at 12563.42,3085.44 h60
  text "GREEN" at 12690.46,3085.44 h60
  text "OTHER" at 13308.46,3085.44 h60
  text "SOLDER RESIST COLOR:" at 11484.68,3074.64 h60
  text "X" at 12563.42,2915.44 h60
  text "MATTE" at 12690.46,2915.44 h60
  text "SEMI-GLOSS" at 13308,2914.8 h60
  text "IMMERSION GOLD (ENIG)" at 12390.46,2726.92 h60
  text "ENEPIG" at 13728,2723.64 h60
  text "SURFACE FINISH:" at 11329.46,2722.64 h60
  text "X" at 12203.51,2722.64 h60
  text "IMM. TIN/SILVER OR EQUIV" at 11659,2565.64 h60
  text "OTHER" at 13090.46,2565.64 h60
  text "ARRAY/PANEL:" at 11329.46,2386.64 h60
  text "CUT AND TRIM PER M1 BOARD OUTLINE" at 12390.46,2382.35 h60
  text "N.C. ROUTE" at 12390.46,2230.64 h60
  text "X" at 13069.46,2230.64 h60
  text "V. SCORE" at 13256.46,2230.64 h60
  text "CERTIFICATION:" at 11329.46,2093.64 h60
  text "MATERIALS AND WORKMANSHIP FOR ALL PCBS" at 12054.46,2093.64 h60
  text "TO MEET OR EXCEED THE REQUIREMENTS OF:" at 12054.46,1995.64 h60
  text "X" at 11680.96,1859.13 h60
  text "ANSI IPC-A-600F CLASS ->" at 11819.96,1859.13 h60
  text "X" at 13459.02,1859.13 h60
  text "2" at 13577.96,1859.14 h60
  text "1" at 13262.96,1857.64 h60
  text "3" at 13931.96,1857.64 h60
  text "X" at 12495.02,1699.64 h60
  text "RoHS" at 12631.96,1699.64 h60
  text "OTHER" at 13276.36,1699.64 h60
  text "PER ORDER" at 13673.42,1699.64 h60
  text "ALL BOARDS MUST MEET OR EXCEED UL94-V0 REQUIREMENTS." at 11357,1534 h60
  text "PCB MUST BEAR THE UL94V-0 UL REGISTERED MATERIAL ID NUMBER" at 11357,1414 h60
  text "ADDITIONAL REQUIREMENTS:" at 11329.46,1240.64 h60
  text "MICROSECTION:" at 11404.23,1125.64 h60
  text "YES" at 12309.96,1125.64 h60
  text "REQUIRED" at 13171.46,969.49 h60
  text "BARE BOARD ELEC. TEST:" at 11404.23,966.64 h60
  text "NONE" at 12709.96,966.64 h60
  text "X" at 13044.46,966.64 h60
  text "PER ORDER" at 13763.46,966.64 h60
  text ".Layer_Name" at 577,-858.49 h60
M11 Gerber Information:
  lines w10: -292,-930.17 6308,-930.17 ; -292,-726.83 6310,-726.83 ; -292,-523.5 -292,-1133.5 3713,-1133.5 6310,-1133.5 6310,-523.5 -291.5,-523.5 -291.5,-1133.5 1284,-1133.5 ; 2173,-1133.5 2173,-523.5 ; 3440,-726.83 3440,-523.5 ; 4280,-726.83 4280,-523.5 ; 4902,-1140 4902,-937.17
  text "ALL ARTWORK VIEWED FROM TOP SIDE" at -228.5,-655.67 h60
  text "BOARD #:" at 2248,-655.67 h60
  text ".PRJ_Number" at 2793.5,-655.67 h60
  text "REV:" at 3638,-655.67 h60
  text ".PCB_Rev" at 3929.5,-655.67 h60
  text "SVN REV:" at 4476,-655.67 h60
  text ".VersionControl_RevNumber" at 4982,-655.67 h60
  text "LAYER NAME =" at -228.5,-858.49 h60
  text "TID #:" at 2248,-859 h60
  text ".TID" at 2793.5,-859 h60
  text "PLOT NAME =" at -228.5,-1064.34 h60
  text ".plot_File_Name" at 577,-1064.34 h60
  text "GENERATED    :" at 2250,-1064.34 h60
  text ".Print_Date" at 3119.5,-1064.34 h60
  text ".Print_Time" at 3848.5,-1064.34 h60
  text "TEXAS INSTRUMENTS" at 5113,-1064.34 h60
M12 Stackup:
  drawing of 191 lines, arcs and shapes, not listed
  text "Layer" at 9752.5,7792.5 h60
  text "Name" at 10162.41,7792.5 h60
  text "Material" at 11092.16,7792.5 h60
  text "Thickness" at 11951.92,7792.5 h60
  text "Constant" at 12601.76,7792.5 h60
  text "Board Layer Stack" at 13171.62,7792.5 h60
  text "1" at 9752.5,7672.5 h60
  text "Top Overlay" at 10162.41,7672.5 h60
  text "2" at 9752.5,7552.5 h60
  text "Top Solder" at 10162.41,7552.5 h60
  text "Solder Resist" at 11092.16,7552.5 h60
  text "0.40mil" at 11951.92,7552.5 h60
  text "3.5" at 12601.76,7552.5 h60
  text "3" at 9752.5,7432.5 h60
  text "Top Layer" at 10162.41,7432.5 h60
  text "Copper" at 11092.16,7432.5 h60
  text "1.40mil" at 11951.92,7432.5 h60
  text "4" at 9752.5,7312.5 h60
  text "Dielectric1" at 10162.41,7312.5 h60
  text "FR-4" at 11092.16,7312.5 h60
  text "59.20mil" at 11951.92,7312.5 h60
  text "4.8" at 12601.76,7312.5 h60
  text "5" at 9752.5,7192.5 h60
  text "Bottom Layer" at 10162.41,7192.5 h60
  text "Copper" at 11092.16,7192.5 h60
  text "1.40mil" at 11951.92,7192.5 h60
  text "6" at 9752.5,7072.5 h60
  text "Bottom Solder" at 10162.41,7072.5 h60
  text "Solder Resist" at 11092.16,7072.5 h60
  text "0.40mil" at 11951.92,7072.5 h60
  text "3.5" at 12601.76,7072.5 h60
  text "7" at 9752.5,6952.5 h60
  text "Bottom Overlay" at 10162.41,6952.5 h60
  text ".Layer_Name" at 577,-858.49 h60
M13 Component Bodies Top:
  text ".Layer_Name" at 577,-858.49 h60
M14 Component Bodies Bottom:
  text ".Layer_Name" at 577,-858.49 h60
M15 Courtyards Top:
  text ".Layer_Name" at 577,-858.49 h60
M16 Courtyards Bottom:
  text ".Layer_Name" at 577,-858.49 h60
Drill Drawing:
  drawing of 157 lines, arcs and shapes, not listed
  text "Hole Tolerance (-)" at 9518.7,5505.03 h36.11 r90
  text "Hole Tolerance (+)" at 9518.7,4820.16 h36.11 r90
  text "Description" at 9518.7,4375.98 h36.11 r90
  text "Template" at 9518.7,4034.09 h36.11 r90
  text "s157h102" at 9593.94,4034.09 h30.1 r90
  text "c165h110" at 9669.18,4034.09 h30.1 r90
  text "c383h255" at 9744.41,4034.09 h30.1 r90
  text "(Mixed)" at 9819.65,4034.09 h30.1 r90
  text "c135h90" at 9894.89,4034.09 h30.1 r90
  text "(Mixed)" at 9970.13,4034.09 h30.1 r90
  text "(Mixed)" at 10045.36,4034.09 h30.1 r90
  text "c800h320" at 10120.6,4034.09 h30.1 r90
  text "(Mixed)" at 10195.84,4034.09 h30.1 r90
  text "c188h125" at 10271.08,4034.09 h30.1 r90
  text "c221h160" at 10346.31,4034.09 h30.1 r90
  text "(Mixed)" at 10421.55,4034.09 h30.1 r90
  text "v51h25" at 10496.79,4034.09 h30.1 r90
  text "v76h38" at 10572.03,4034.09 h30.1 r90
  text "Pad Shape" at 9518.7,3644.06 h36.11 r90
  text "Rectangle" at 9593.94,3644.06 h30.1 r90
  text "Rounded" at 9669.18,3644.06 h30.1 r90
  text "Rounded" at 9744.41,3644.06 h30.1 r90
  text "(Mixed)" at 9819.65,3644.06 h30.1 r90
  text "Rounded" at 9894.89,3644.06 h30.1 r90
  text "(Mixed)" at 9970.13,3644.06 h30.1 r90
  text "(Mixed)" at 10045.36,3644.06 h30.1 r90
  text "Rounded" at 10120.6,3644.06 h30.1 r90
  text "(Mixed)" at 10195.84,3644.06 h30.1 r90
  text "Rounded" at 10271.08,3644.06 h30.1 r90
  text "Rounded" at 10346.31,3644.06 h30.1 r90
  text "(Mixed)" at 10421.55,3644.06 h30.1 r90
  text "Rounded" at 10496.79,3644.06 h30.1 r90
  text "Rounded" at 10572.03,3644.06 h30.1 r90
  text "Via/Pad" at 9518.7,3332.25 h36.11 r90
  text "Pad" at 9593.94,3332.25 h30.1 r90
  text "Pad" at 9669.18,3332.25 h30.1 r90
  text "Pad" at 9744.41,3332.25 h30.1 r90
  text "Pad" at 9819.65,3332.25 h30.1 r90
  text "Pad" at 9894.89,3332.25 h30.1 r90
  text "Pad" at 9970.13,3332.25 h30.1 r90
  text "Pad" at 10045.36,3332.25 h30.1 r90
  text "Pad" at 10120.6,3332.25 h30.1 r90
  text "Pad" at 10195.84,3332.25 h30.1 r90
  text "Pad" at 10271.08,3332.25 h30.1 r90
  text "Pad" at 10346.31,3332.25 h30.1 r90
  text "Pad" at 10421.55,3332.25 h30.1 r90
  text "Via" at 10496.79,3332.25 h30.1 r90
  text "Via" at 10572.03,3332.25 h30.1 r90
  text "Drill Layer Pair" at 9518.7,2570.13 h36.11 r90
  text "Top Layer - Bottom Layer" at 9593.94,2570.13 h30.1 r90
  text "Top Layer - Bottom Layer" at 9669.18,2570.13 h30.1 r90
  text "Top Layer - Bottom Layer" at 9744.41,2570.13 h30.1 r90
  text "Top Layer - Bottom Layer" at 9819.65,2570.13 h30.1 r90
  text "Top Layer - Bottom Layer" at 9894.89,2570.13 h30.1 r90
  text "Top Layer - Bottom Layer" at 9970.13,2570.13 h30.1 r90
  text "Top Layer - Bottom Layer" at 10045.36,2570.13 h30.1 r90
  text "Top Layer - Bottom Layer" at 10120.6,2570.13 h30.1 r90
  text "Top Layer - Bottom Layer" at 10195.84,2570.13 h30.1 r90
  text "Top Layer - Bottom Layer" at 10271.08,2570.13 h30.1 r90
  text "Top Layer - Bottom Layer" at 10346.31,2570.13 h30.1 r90
  text "Top Layer - Bottom Layer" at 10421.55,2570.13 h30.1 r90
  text "Top Layer - Bottom Layer" at 10496.79,2570.13 h30.1 r90
  text "Top Layer - Bottom Layer" at 10572.03,2570.13 h30.1 r90
  text "Hole Type" at 9518.7,2186.11 h36.11 r90
  text "Round" at 9593.94,2186.11 h30.1 r90
  text "Round" at 9669.18,2186.11 h30.1 r90
  text "Round" at 9744.41,2186.11 h30.1 r90
  text "Round" at 9819.65,2186.11 h30.1 r90
  text "Round" at 9894.89,2186.11 h30.1 r90
  text "Round" at 9970.13,2186.11 h30.1 r90
  text "Round" at 10045.36,2186.11 h30.1 r90
  text "Round" at 10120.6,2186.11 h30.1 r90
  text "Round" at 10195.84,2186.11 h30.1 r90
  text "Round" at 10271.08,2186.11 h30.1 r90
  text "Round" at 10346.31,2186.11 h30.1 r90
  text "Round" at 10421.55,2186.11 h30.1 r90
  text "Round" at 10496.79,2186.11 h30.1 r90
  text "Round" at 10572.03,2186.11 h30.1 r90
  text "Plated" at 9518.7,1916.42 h36.11 r90
  text "PTH" at 9593.94,1916.42 h30.1 r90
  text "PTH" at 9669.18,1916.42 h30.1 r90
  text "PTH" at 9744.41,1916.42 h30.1 r90
  text "PTH" at 9819.65,1916.42 h30.1 r90
  text "PTH" at 9894.89,1916.42 h30.1 r90
  text "PTH" at 9970.13,1916.42 h30.1 r90
  text "PTH" at 10045.36,1916.42 h30.1 r90
  text "PTH" at 10120.6,1916.42 h30.1 r90
  text "PTH" at 10195.84,1916.42 h30.1 r90
  text "PTH" at 10271.08,1916.42 h30.1 r90
  text "PTH" at 10346.31,1916.42 h30.1 r90
  text "PTH" at 10421.55,1916.42 h30.1 r90
  text "PTH" at 10496.79,1916.42 h30.1 r90
  text "PTH" at 10572.03,1916.42 h30.1 r90
  text "Hole Size" at 9518.7,1329.8 h36.11 r90
  text "40.00mil (1.016mm)" at 9593.94,1329.8 h30.1 r90
  text "43.31mil (1.100mm)" at 9669.18,1329.8 h30.1 r90
  text "100.39mil (2.550mm)" at 9744.41,1329.8 h30.1 r90
  text "40.16mil (1.020mm)" at 9819.65,1329.8 h30.1 r90
  text "35.43mil (0.900mm)" at 9894.89,1329.8 h30.1 r90
  text "50.00mil (1.270mm)" at 9970.13,1329.8 h30.1 r90
  text "62.00mil (1.575mm)" at 10045.36,1329.8 h30.1 r90
  text "125.98mil (3.200mm)" at 10120.6,1329.8 h30.1 r90
  text "33.47mil (0.850mm)" at 10195.84,1329.8 h30.1 r90
  text "49.21mil (1.250mm)" at 10271.08,1329.8 h30.1 r90
  text "63.00mil (1.600mm)" at 10346.31,1329.8 h30.1 r90
  text "51.18mil (1.300mm)" at 10421.55,1329.8 h30.1 r90
  text "10.00mil (0.254mm)" at 10496.79,1329.8 h30.1 r90
  text "15.00mil (0.381mm)" at 10572.03,1329.8 h30.1 r90
  text "Count" at 9518.7,1018.96 h36.11 r90
  text "4" at 9593.94,1018.96 h30.1 r90
  text "4" at 9669.18,1018.96 h30.1 r90
  text "4" at 9744.41,1018.96 h30.1 r90
  text "7" at 9819.65,1018.96 h30.1 r90
  text "8" at 9894.89,1018.96 h30.1 r90
  text "8" at 9970.13,1018.96 h30.1 r90
  text "8" at 10045.36,1018.96 h30.1 r90
  text "8" at 10120.6,1018.96 h30.1 r90
  text "12" at 10195.84,1018.96 h30.1 r90
  text "12" at 10271.08,1018.96 h30.1 r90
  text "13" at 10346.31,1018.96 h30.1 r90
  text "18" at 10421.55,1018.96 h30.1 r90
  text "35" at 10496.79,1018.96 h30.1 r90
  text "666" at 10572.03,1018.96 h30.1 r90
  text "807 Total" at 10647.27,1018.96 h30.1 r90
  text "Symbol" at 9518.7,749.27 h36.11 r90
  text ".Layer_Name" at 577,-858.49 h60
M17 Embedded Cavity:
  text ".Layer_Name" at 577,-858.49 h60
M18 Embedded Assembly:
  text ".Layer_Name" at 577,-858.49 h60
M19 Embedded Keepout:
  text ".Layer_Name" at 577,-858.49 h60

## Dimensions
0,-400 to 1000,-400 on M2 Board Dimensions
0,0 to 0,6929.13 on M2 Board Dimensions
0,0 to 7874.02,0 on M2 Board Dimensions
